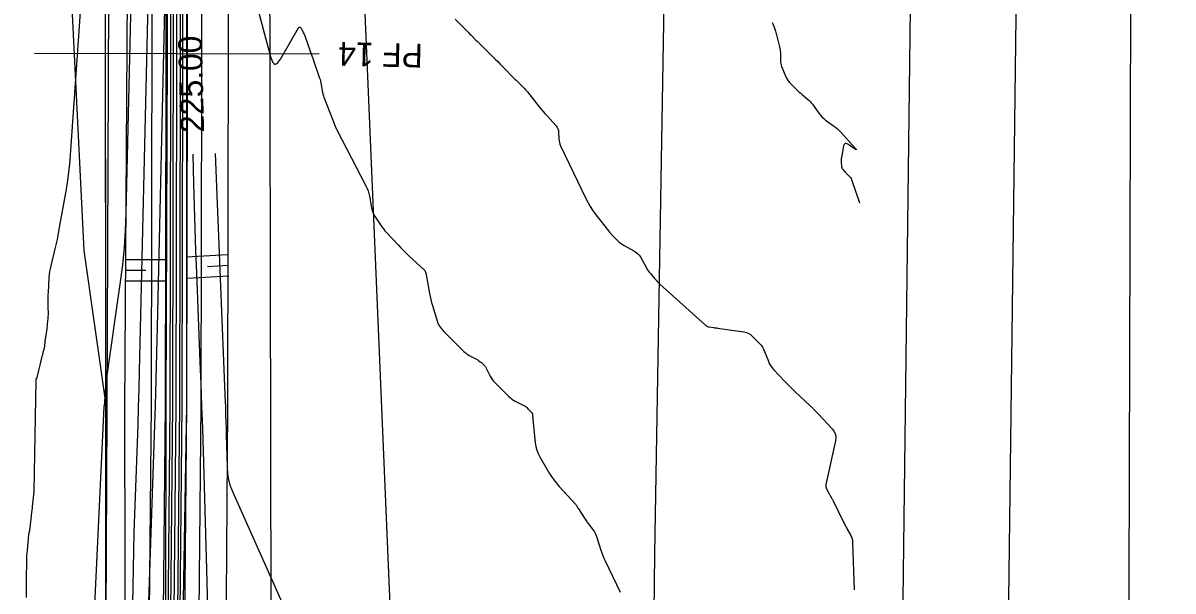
# Model space of a CAD drawing. Extents: x -534410 to -534262, y -1190162 to -1189584.
# Drawn here: x -534372.92 to -534324.46, y -1189828.34 to -1189804.39 of the extents above; entities that cross this region are included whole.
import ezdxf

# ---------------------------------------------------------------- set-up
doc = ezdxf.new("R2010")
doc.units = 0
for name, color, linetype in [('30', 7, 'Continuous'), ('31', 7, 'Continuous'), ('40', 7, 'Continuous'), ('_linie', 7, 'Continuous'), ('_N_osa', 7, 'Continuous'), ('_N_tenká', 7, 'Continuous'), ('_N_tenká_velmi', 7, 'Continuous'), ('_N_text', 7, 'Continuous'), ('_tenka', 7, 'Continuous'), ('_velmi_tenka', 7, 'Continuous'), ('Default', 7, 'Continuous'), ('Hranice parcel', 7, 'Continuous')]:
    doc.layers.add(name, color=color, linetype=linetype)

msp = doc.modelspace()

# ---------------------------------------------------------------- linework, layer by layer
at = {"layer": '30'}
for points in [[(-534370.569, -1189843.242), (-534369.518, -1189820.88), (-534369.518, -1189820.872), (-534369.517, -1189820.856), (-534369.517, -1189820.836), (-534369.516, -1189820.816), (-534369.516, -1189820.799), (-534369.515, -1189820.777), (-534369.515, -1189820.744), (-534369.514, -1189820.737), (-534369.51, -1189820.699), (-534369.509, -1189820.687), (-534369.509, -1189820.685), (-534369.507, -1189820.597), (-534369.506, -1189820.595), (-534369.501, -1189820.574), (-534369.5, -1189820.569), (-534369.499, -1189820.562), (-534369.498, -1189820.55), (-534369.497, -1189820.542), (-534369.497, -1189820.525), (-534369.496, -1189820.51), (-534369.495, -1189820.503), (-534369.49, -1189820.484), (-534369.488, -1189820.474), (-534369.482, -1189820.439), (-534369.481, -1189820.432), (-534369.48, -1189820.425), (-534369.479, -1189820.418), (-534369.479, -1189820.411), (-534369.457, -1189820.094), (-534369.447, -1189819.956), (-534369.431, -1189819.725), (-534369.427, -1189819.679), (-534369.423, -1189819.633), (-534369.418, -1189819.587), (-534369.412, -1189819.541), (-534368.811, -1189815.306), (-534368.719, -1189814.585), (-534368.649, -1189813.861), (-534368.6, -1189813.136), (-534368.572, -1189812.408), (-534367.974, -1189786.766)], [(-534367.679, -1189830.441), (-534367.447, -1189823.822), (-534367.391, -1189822.167), (-534367.34, -1189820.512), (-534367.294, -1189818.856), (-534367.253, -1189817.201), (-534366.829, -1189798.889), (-534366.819, -1189798.744), (-534366.799, -1189798.695), (-534366.77, -1189798.739), (-534366.73, -1189798.878), (-534366.506, -1189799.806), (-534366.479, -1189799.878), (-534366.444, -1189799.907), (-534366.402, -1189799.892), (-534366.351, -1189799.834), (-534366.134, -1189799.511), (-534366.086, -1189799.452), (-534366.051, -1189799.438), (-534366.029, -1189799.469), (-534366.02, -1189799.544), (-534365.914, -1189803.919)], [(-534363.773, -1189801.02), (-534362.475, -1189805.863), (-534362.398, -1189806.061), (-534362.304, -1189806.136), (-534362.194, -1189806.088), (-534362.068, -1189805.917), (-534361.308, -1189804.604), (-534361.285, -1189804.574), (-534361.262, -1189804.564), (-534361.239, -1189804.574), (-534361.216, -1189804.604), (-534361.126, -1189804.764), (-534361.104, -1189804.805), (-534361.084, -1189804.846), (-534361.066, -1189804.888), (-534361.049, -1189804.931), (-534360.731, -1189805.817), (-534360.725, -1189805.835), (-534360.714, -1189805.87), (-534360.708, -1189805.887), (-534360.427, -1189806.713), (-534360.405, -1189806.779), (-534360.387, -1189806.846), (-534360.372, -1189806.914), (-534360.359, -1189806.982), (-534360.315, -1189807.257), (-534360.302, -1189807.325), (-534360.286, -1189807.392), (-534360.266, -1189807.458), (-534360.242, -1189807.524), (-534359.746, -1189808.806), (-534359.745, -1189808.811), (-534359.742, -1189808.815), (-534359.74, -1189808.819), (-534359.737, -1189808.823), (-534359.725, -1189808.837), (-534359.723, -1189808.841), (-534359.72, -1189808.845), (-534359.718, -1189808.849), (-534359.716, -1189808.853), (-534359.707, -1189808.874), (-534359.703, -1189808.884), (-534359.698, -1189808.894), (-534358.473, -1189811.259), (-534358.423, -1189811.364), (-534358.382, -1189811.472), (-534358.349, -1189811.583), (-534358.324, -1189811.697), (-534358.236, -1189812.185), (-534358.213, -1189812.284), (-534358.18, -1189812.38), (-534358.138, -1189812.472), (-534358.085, -1189812.56), (-534357.857, -1189812.905), (-534357.798, -1189812.99), (-534357.736, -1189813.072), (-534357.671, -1189813.151), (-534357.602, -1189813.228), (-534357.102, -1189813.762), (-534356.994, -1189813.875), (-534356.885, -1189813.986), (-534356.773, -1189814.096), (-534356.66, -1189814.204), (-534356.01, -1189814.812), (-534355.994, -1189814.829), (-534355.981, -1189814.848), (-534355.971, -1189814.868), (-534355.964, -1189814.891), (-534355.939, -1189814.983), (-534355.934, -1189815.006), (-534355.928, -1189815.029), (-534355.923, -1189815.052), (-534355.919, -1189815.076), (-534355.789, -1189815.792), (-534355.764, -1189815.919), (-534355.736, -1189816.045), (-534355.704, -1189816.17), (-534355.669, -1189816.295), (-534355.486, -1189816.902), (-534355.435, -1189817.04), (-534355.369, -1189817.169), (-534355.287, -1189817.288), (-534355.19, -1189817.398), (-534354.347, -1189818.241), (-534354.295, -1189818.289), (-534354.24, -1189818.332), (-534354.182, -1189818.371), (-534354.121, -1189818.406), (-534353.782, -1189818.581), (-534353.763, -1189818.591), (-534353.744, -1189818.603), (-534353.727, -1189818.615), (-534353.71, -1189818.628), (-534353.643, -1189818.683), (-534353.626, -1189818.697), (-534353.609, -1189818.711), (-534353.593, -1189818.725), (-534353.576, -1189818.739), (-534353.49, -1189818.811), (-534353.472, -1189818.829), (-534353.455, -1189818.848), (-534353.44, -1189818.869), (-534353.428, -1189818.891), (-534353.232, -1189819.283), (-534353.192, -1189819.354), (-534353.148, -1189819.421), (-534353.098, -1189819.485), (-534353.043, -1189819.545), (-534352.443, -1189820.144), (-534352.384, -1189820.199), (-534352.32, -1189820.249), (-534352.253, -1189820.294), (-534352.182, -1189820.333), (-534351.789, -1189820.529), (-534351.767, -1189820.542), (-534351.746, -1189820.556), (-534351.726, -1189820.572), (-534351.708, -1189820.59), (-534351.637, -1189820.665), (-534351.619, -1189820.684), (-534351.601, -1189820.702), (-534351.582, -1189820.72), (-534351.564, -1189820.738), (-534351.488, -1189820.809), (-534351.472, -1189820.828), (-534351.459, -1189820.849), (-534351.451, -1189820.871), (-534351.448, -1189820.896), (-534351.438, -1189821.077), (-534351.436, -1189821.115), (-534351.433, -1189821.154), (-534351.429, -1189821.192), (-534351.426, -1189821.231), (-534351.336, -1189822.093), (-534351.312, -1189822.246), (-534351.272, -1189822.395), (-534351.217, -1189822.539), (-534351.145, -1189822.677), (-534350.745, -1189823.362), (-534350.652, -1189823.512), (-534350.551, -1189823.656), (-534350.442, -1189823.795), (-534350.326, -1189823.928), (-534349.634, -1189824.681), (-534349.621, -1189824.696), (-534349.61, -1189824.711), (-534349.599, -1189824.727), (-534349.59, -1189824.743), (-534349.553, -1189824.811), (-534349.543, -1189824.828), (-534349.534, -1189824.844), (-534349.524, -1189824.861), (-534349.513, -1189824.877), (-534349.232, -1189825.312), (-534349.192, -1189825.373), (-534349.15, -1189825.433), (-534349.108, -1189825.492), (-534349.064, -1189825.551), (-534348.886, -1189825.783), (-534348.845, -1189825.842), (-534348.808, -1189825.905), (-534348.778, -1189825.97), (-534348.753, -1189826.038), (-534348.571, -1189826.608), (-534348.532, -1189826.725), (-534348.488, -1189826.841), (-534348.44, -1189826.956), (-534348.389, -1189827.068), (-534347.756, -1189828.386)], [(-534341.357, -1189804.378), (-534341.328, -1189804.425), (-534341.303, -1189804.474), (-534341.283, -1189804.526), (-534341.21, -1189804.738), (-534341.193, -1189804.792), (-534341.177, -1189804.845), (-534341.162, -1189804.899), (-534341.149, -1189804.954), (-534341.034, -1189805.456), (-534341.021, -1189805.52), (-534341.012, -1189805.584), (-534341.006, -1189805.649), (-534341.005, -1189805.714), (-534341.005, -1189805.975), (-534341.001, -1189806.04), (-534340.992, -1189806.103), (-534340.976, -1189806.165), (-534340.953, -1189806.226), (-534340.756, -1189806.69), (-534340.72, -1189806.765), (-534340.677, -1189806.835), (-534340.627, -1189806.9), (-534340.57, -1189806.961), (-534340.318, -1189807.205), (-534340.263, -1189807.257), (-534340.207, -1189807.308), (-534340.15, -1189807.358), (-534340.092, -1189807.407), (-534339.86, -1189807.601), (-534339.803, -1189807.651), (-534339.75, -1189807.705), (-534339.701, -1189807.761), (-534339.655, -1189807.821), (-534339.384, -1189808.199), (-534339.321, -1189808.279), (-534339.252, -1189808.353), (-534339.177, -1189808.422), (-534339.097, -1189808.485), (-534338.764, -1189808.725), (-534338.682, -1189808.787), (-534338.604, -1189808.853), (-534338.53, -1189808.923), (-534338.46, -1189808.997), (-534337.857, -1189809.666), (-534337.816, -1189809.715), (-534337.807, -1189809.737), (-534337.83, -1189809.731), (-534337.885, -1189809.697), (-534338.168, -1189809.506), (-534338.231, -1189809.475), (-534338.281, -1189809.476), (-534338.318, -1189809.511), (-534338.34, -1189809.578), (-534338.43, -1189810.063), (-534338.437, -1189810.108), (-534338.441, -1189810.153), (-534338.442, -1189810.198), (-534338.44, -1189810.243), (-534338.425, -1189810.446), (-534338.419, -1189810.48), (-534338.409, -1189810.511), (-534338.394, -1189810.54), (-534338.374, -1189810.568), (-534338.278, -1189810.678), (-534338.257, -1189810.701), (-534338.236, -1189810.724), (-534338.214, -1189810.746), (-534338.191, -1189810.767), (-534338.061, -1189810.89), (-534338.056, -1189810.895), (-534338.051, -1189810.901), (-534338.042, -1189810.912), (-534338.039, -1189810.918), (-534338.036, -1189810.925), (-534338.021, -1189810.966), (-534338.014, -1189810.986), (-534337.672, -1189811.971)], [(-534365.768, -1189809.917), (-534365.737, -1189811.175), (-534365.712, -1189812.112), (-534365.684, -1189813.05), (-534365.652, -1189813.987), (-534365.616, -1189814.925), (-534365.465, -1189818.673), (-534365.429, -1189819.611), (-534365.395, -1189820.548), (-534365.365, -1189821.485), (-534365.337, -1189822.423), (-534365.18, -1189827.933), (-534365.145, -1189829.164)]]:
    msp.add_lwpolyline(points, dxfattribs=at)
at = {"layer": '31'}
for points in [[(-534368.595, -1189844.62), (-534368.288, -1189828.137), (-534368.272, -1189827.381), (-534368.254, -1189826.626), (-534368.232, -1189825.87), (-534368.207, -1189825.115), (-534368.101, -1189822.093), (-534368.075, -1189821.337), (-534368.052, -1189820.581), (-534368.031, -1189819.826), (-534368.012, -1189819.07), (-534367.528, -1189798.201), (-534367.485, -1189796.321), (-534367.441, -1189794.441), (-534367.397, -1189792.561), (-534367.353, -1189790.681), (-534367.147, -1189781.836), (-534367.116, -1189780.619), (-534367.081, -1189779.401), (-534367.07, -1189779.047)], [(-534372.78, -1189828.611), (-534372.773, -1189827.888), (-534372.772, -1189827.86), (-534372.771, -1189827.816), (-534372.771, -1189827.802), (-534372.764, -1189827.078), (-534372.761, -1189826.961), (-534372.756, -1189826.845), (-534372.749, -1189826.729), (-534372.739, -1189826.612), (-534372.676, -1189825.962), (-534372.674, -1189825.939), (-534372.67, -1189825.916), (-534372.666, -1189825.893), (-534372.662, -1189825.871), (-534372.642, -1189825.78), (-534372.638, -1189825.757), (-534372.634, -1189825.734), (-534372.63, -1189825.711), (-534372.627, -1189825.688), (-534372.547, -1189825.022), (-534372.537, -1189824.933), (-534372.527, -1189824.844), (-534372.517, -1189824.756), (-534372.508, -1189824.667), (-534372.455, -1189824.138), (-534372.454, -1189824.131), (-534372.451, -1189824.117), (-534372.45, -1189824.109), (-534372.373, -1189819.451), (-534372.372, -1189819.44), (-534372.37, -1189819.429), (-534372.367, -1189819.419), (-534372.362, -1189819.409), (-534372.341, -1189819.371), (-534372.336, -1189819.361), (-534372.332, -1189819.351), (-534372.329, -1189819.34), (-534372.326, -1189819.33), (-534372.098, -1189818.396), (-534372.091, -1189818.365), (-534372.083, -1189818.334), (-534372.075, -1189818.303), (-534372.067, -1189818.272), (-534372.034, -1189818.148), (-534372.026, -1189818.117), (-534372.02, -1189818.086), (-534372.014, -1189818.054), (-534372.01, -1189818.023), (-534371.989, -1189817.823), (-534371.984, -1189817.779), (-534371.979, -1189817.735), (-534371.973, -1189817.691), (-534371.966, -1189817.648), (-534371.912, -1189817.287), (-534371.905, -1189817.233), (-534371.898, -1189817.179), (-534371.891, -1189817.125), (-534371.886, -1189817.07), (-534371.864, -1189816.853), (-534371.86, -1189816.799), (-534371.857, -1189816.744), (-534371.855, -1189816.69), (-534371.855, -1189816.635), (-534371.857, -1189816.371), (-534371.857, -1189816.321), (-534371.858, -1189816.271), (-534371.858, -1189816.221), (-534371.859, -1189816.171), (-534371.861, -1189815.971), (-534371.861, -1189815.921), (-534371.861, -1189815.871), (-534371.859, -1189815.821), (-534371.856, -1189815.771), (-534371.815, -1189815.121), (-534371.805, -1189814.996), (-534371.789, -1189814.873), (-534371.767, -1189814.75), (-534371.74, -1189814.628), (-534371.551, -1189813.856), (-534371.511, -1189813.686), (-534371.474, -1189813.516), (-534371.44, -1189813.345), (-534371.408, -1189813.174), (-534371.096, -1189811.391), (-534371.039, -1189811.036), (-534370.99, -1189810.68), (-534370.952, -1189810.323), (-534370.922, -1189809.965), (-534369.649, -1189791.643)], [(-534354.713, -1189804.225), (-534354.19, -1189804.755), (-534354.145, -1189804.8), (-534354.101, -1189804.844), (-534354.056, -1189804.889), (-534354.011, -1189804.934), (-534353.833, -1189805.113), (-534353.788, -1189805.158), (-534353.743, -1189805.202), (-534353.698, -1189805.247), (-534353.653, -1189805.291), (-534353.124, -1189805.815), (-534353.021, -1189805.917), (-534352.918, -1189806.019), (-534352.816, -1189806.122), (-534352.713, -1189806.225), (-534352.19, -1189806.754), (-534352.146, -1189806.799), (-534352.101, -1189806.844), (-534352.056, -1189806.889), (-534352.012, -1189806.934), (-534351.833, -1189807.113), (-534351.789, -1189807.158), (-534351.746, -1189807.205), (-534351.704, -1189807.253), (-534351.664, -1189807.301), (-534351.166, -1189807.923), (-534351.089, -1189808.019), (-534351.011, -1189808.113), (-534350.931, -1189808.206), (-534350.85, -1189808.297), (-534350.457, -1189808.735), (-534350.413, -1189808.792), (-534350.381, -1189808.854), (-534350.361, -1189808.92), (-534350.352, -1189808.992), (-534350.338, -1189809.286), (-534350.331, -1189809.358), (-534350.317, -1189809.429), (-534350.296, -1189809.498), (-534350.268, -1189809.566), (-534349.192, -1189811.818), (-534349.111, -1189811.976), (-534349.022, -1189812.129), (-534348.925, -1189812.278), (-534348.82, -1189812.421), (-534348.256, -1189813.15), (-534348.209, -1189813.207), (-534348.161, -1189813.263), (-534348.111, -1189813.317), (-534348.06, -1189813.37), (-534347.849, -1189813.577), (-534347.794, -1189813.627), (-534347.737, -1189813.672), (-534347.677, -1189813.714), (-534347.614, -1189813.752), (-534347.182, -1189813.992), (-534347.094, -1189814.049), (-534347.016, -1189814.117), (-534346.948, -1189814.195), (-534346.891, -1189814.283), (-534346.651, -1189814.715), (-534346.614, -1189814.779), (-534346.573, -1189814.84), (-534346.529, -1189814.9), (-534346.483, -1189814.957), (-534346.291, -1189815.183), (-534346.242, -1189815.239), (-534346.191, -1189815.293), (-534346.139, -1189815.345), (-534346.085, -1189815.396), (-534344.156, -1189817.133), (-534344.122, -1189817.16), (-534344.085, -1189817.181), (-534344.046, -1189817.196), (-534344.004, -1189817.205), (-534343.83, -1189817.23), (-534343.787, -1189817.236), (-534343.743, -1189817.243), (-534343.7, -1189817.249), (-534343.656, -1189817.255), (-534342.55, -1189817.412), (-534342.449, -1189817.435), (-534342.356, -1189817.472), (-534342.27, -1189817.524), (-534342.191, -1189817.592), (-534341.893, -1189817.891), (-534341.822, -1189817.969), (-534341.762, -1189818.052), (-534341.71, -1189818.142), (-534341.668, -1189818.238), (-534341.513, -1189818.643), (-534341.471, -1189818.741), (-534341.419, -1189818.833), (-534341.359, -1189818.92), (-534341.289, -1189819.001), (-534340.821, -1189819.499), (-534340.718, -1189819.608), (-534340.613, -1189819.714), (-534340.506, -1189819.819), (-534340.398, -1189819.923), (-534339.763, -1189820.519), (-534339.625, -1189820.649), (-534339.605, -1189820.668), (-534339.586, -1189820.687), (-534339.567, -1189820.706), (-534339.548, -1189820.726), (-534339.399, -1189820.884), (-534338.821, -1189821.499), (-534338.736, -1189821.613), (-534338.684, -1189821.736), (-534338.665, -1189821.868), (-534338.681, -1189822.01), (-534339.088, -1189823.852), (-534339.094, -1189823.899), (-534339.092, -1189823.945), (-534339.081, -1189823.99), (-534339.062, -1189824.033), (-534338.946, -1189824.242), (-534338.932, -1189824.266), (-534338.919, -1189824.289), (-534338.905, -1189824.313), (-534338.891, -1189824.337), (-534338.836, -1189824.432), (-534338.823, -1189824.456), (-534338.81, -1189824.48), (-534338.797, -1189824.504), (-534338.785, -1189824.529), (-534338.329, -1189825.459), (-534338.295, -1189825.528), (-534338.26, -1189825.596), (-534338.225, -1189825.664), (-534338.189, -1189825.732), (-534338.043, -1189826.003), (-534338.01, -1189826.071), (-534337.987, -1189826.142), (-534337.971, -1189826.216), (-534337.965, -1189826.291), (-534337.898, -1189828.283)], [(-534364.821, -1189809.894), (-534364.399, -1189820.399), (-534364.395, -1189820.511), (-534364.391, -1189820.623), (-534364.387, -1189820.734), (-534364.384, -1189820.846), (-534364.371, -1189821.294), (-534364.368, -1189821.406), (-534364.365, -1189821.518), (-534364.362, -1189821.63), (-534364.359, -1189821.742), (-534364.324, -1189823.12), (-534364.305, -1189823.384), (-534364.26, -1189823.643), (-534364.189, -1189823.896), (-534364.093, -1189824.142), (-534361.369, -1189830.256)]]:
    msp.add_lwpolyline(points, dxfattribs=at)
at = {"layer": '_linie'}
for points in [[(-534366.12, -1189620.81), (-534364.52, -1189627.2), (-534365.69, -1189653.8), (-534366.76, -1189684.81), (-534368.14, -1189748.73), (-534368.38, -1189779.14), (-534368.65, -1189820.64), (-534368.59, -1189847.58), (-534367.2, -1189913.8)], [(-534363.12, -1189621.02), (-534362.79, -1189621.58), (-534361.82, -1189627.79), (-534363.46, -1189653.55), (-534365.47, -1189684.77), (-534366.65, -1189748.83), (-534366.75, -1189779.47), (-534366.9, -1189820.47), (-534366.95, -1189846.72), (-534366.338, -1189888.804), (-534363.85, -1189911.95), (-534357.07, -1189929.19), (-534352.334, -1189940.856)], [(-534359.03, -1189621.26), (-534359.41, -1189621.83), (-534360.84, -1189627.76), (-534362.92, -1189653.56), (-534364.64, -1189685), (-534365.94, -1189748.9), (-534366.02, -1189779.52), (-534366.03, -1189820.5), (-534366.48, -1189846.73), (-534365.511, -1189888.873), (-534362.72, -1189912.12), (-534356.62, -1189928.64), (-534351.589, -1189940.594)]]:
    msp.add_lwpolyline(points, dxfattribs=at)
at = {"layer": '_N_osa'}
msp.add_lwpolyline([(-534351.95, -1189940.722), (-534356.845, -1189928.915), (-534363.285, -1189912.035), (-534365.925, -1189888.838), (-534366.715, -1189846.725), (-534366.465, -1189820.485), (-534366.385, -1189779.495), (-534366.295, -1189748.865), (-534365.055, -1189684.885), (-534363.19, -1189653.555), (-534361.333, -1189627.822)], dxfattribs=at)
at = {"layer": '_N_tenká'}
for points in [[(-534352.92, -1189941.124), (-534357.821, -1189929.303), (-534364.313, -1189912.285), (-534366.973, -1189888.908), (-534367.765, -1189846.73), (-534367.515, -1189820.479), (-534367.435, -1189779.492), (-534367.345, -1189748.853), (-534366.104, -1189684.844), (-534364.238, -1189653.486), (-534362.424, -1189628.352), (-534361.782, -1189627.792)], [(-534352.089, -1189940.779), (-534356.984, -1189928.97), (-534363.432, -1189912.071), (-534366.074, -1189888.848), (-534366.865, -1189846.726), (-534366.615, -1189820.484), (-534366.535, -1189779.495), (-534366.445, -1189748.863), (-534365.205, -1189684.879), (-534363.34, -1189653.545), (-534361.483, -1189627.812)], [(-534351.812, -1189940.664), (-534356.706, -1189928.86), (-534363.138, -1189911.999), (-534365.775, -1189888.828), (-534366.565, -1189846.724), (-534366.315, -1189820.486), (-534366.235, -1189779.495), (-534366.145, -1189748.867), (-534364.905, -1189684.891), (-534363.04, -1189653.565), (-534361.184, -1189627.831)], [(-534350.98, -1189940.319), (-534355.869, -1189928.527), (-534362.257, -1189911.785), (-534364.876, -1189888.769), (-534365.665, -1189846.72), (-534365.415, -1189820.491), (-534365.335, -1189779.498), (-534365.245, -1189748.877), (-534364.006, -1189684.926), (-534362.142, -1189653.624), (-534360.329, -1189628.488), (-534360.884, -1189627.851)]]:
    msp.add_lwpolyline(points, dxfattribs=at)
at = {"layer": '_N_tenká_velmi'}
for points in [[(-534352.366, -1189940.894), (-534357.263, -1189929.081), (-534363.726, -1189912.142), (-534366.374, -1189888.868), (-534367.165, -1189846.727), (-534366.915, -1189820.482), (-534366.835, -1189779.494), (-534366.745, -1189748.86), (-534365.505, -1189684.867), (-534363.639, -1189653.525), (-534361.782, -1189627.792)], [(-534352.181, -1189940.817), (-534357.077, -1189929.007), (-534363.53, -1189912.095), (-534366.174, -1189888.855), (-534366.965, -1189846.726), (-534366.715, -1189820.484), (-534366.635, -1189779.494), (-534366.545, -1189748.862), (-534365.305, -1189684.875), (-534363.439, -1189653.539), (-534361.583, -1189627.805)], [(-534351.719, -1189940.626), (-534356.613, -1189928.823), (-534363.04, -1189911.975), (-534365.675, -1189888.822), (-534366.465, -1189846.724), (-534366.215, -1189820.486), (-534366.135, -1189779.496), (-534366.045, -1189748.868), (-534364.805, -1189684.895), (-534362.941, -1189653.571), (-534361.084, -1189627.838)], [(-534351.534, -1189940.549), (-534356.427, -1189928.749), (-534362.844, -1189911.928), (-534365.475, -1189888.808), (-534366.265, -1189846.723), (-534366.015, -1189820.488), (-534365.935, -1189779.496), (-534365.845, -1189748.87), (-534364.605, -1189684.903), (-534362.741, -1189653.585), (-534360.884, -1189627.851)]]:
    msp.add_lwpolyline(points, dxfattribs=at)
at = {"layer": '_N_text'}
msp.add_lwpolyline([(-534360.436, -1189805.703), (-534372.436, -1189805.676)], dxfattribs=at)
at = {"layer": '_tenka'}
for points in [[(-534349.13, -1189939.73), (-534354.63, -1189926.96), (-534362.03, -1189907.65), (-534364.521, -1189888.74), (-534364.47, -1189846.64), (-534364.29, -1189820.63), (-534364.22, -1189780.69), (-534363.18, -1189749.38), (-534362.5, -1189685.39), (-534360.27, -1189651.6), (-534357.03, -1189627.34), (-534354.77, -1189620.37)], [(-534366.12, -1189620.81), (-534364.52, -1189627.2), (-534365.69, -1189653.8), (-534366.76, -1189684.81), (-534368.14, -1189748.73), (-534368.38, -1189779.14), (-534368.65, -1189820.64), (-534368.59, -1189847.58), (-534367.2, -1189913.8)], [(-534366.12, -1189620.81), (-534364.52, -1189627.2), (-534365.69, -1189653.8), (-534366.76, -1189684.81), (-534368.14, -1189748.73), (-534368.38, -1189779.14), (-534368.65, -1189820.64), (-534368.59, -1189847.58), (-534367.2, -1189913.8)], [(-534363.12, -1189621.02), (-534362.79, -1189621.58), (-534361.82, -1189627.79), (-534363.46, -1189653.55), (-534365.47, -1189684.77), (-534366.65, -1189748.83), (-534366.75, -1189779.47), (-534366.9, -1189820.47), (-534366.95, -1189846.72), (-534366.338, -1189888.804), (-534363.85, -1189911.95), (-534357.07, -1189929.19), (-534352.334, -1189940.856)], [(-534363.12, -1189621.02), (-534362.79, -1189621.58), (-534361.82, -1189627.79), (-534363.46, -1189653.55), (-534365.47, -1189684.77), (-534366.65, -1189748.83), (-534366.75, -1189779.47), (-534366.9, -1189820.47), (-534366.95, -1189846.72), (-534366.338, -1189888.804), (-534363.85, -1189911.95), (-534357.07, -1189929.19), (-534352.334, -1189940.856)], [(-534359.03, -1189621.26), (-534359.41, -1189621.83), (-534360.84, -1189627.76), (-534362.92, -1189653.56), (-534364.64, -1189685), (-534365.94, -1189748.9), (-534366.02, -1189779.52), (-534366.03, -1189820.5), (-534366.48, -1189846.73), (-534365.511, -1189888.873), (-534362.72, -1189912.12), (-534356.62, -1189928.64), (-534351.589, -1189940.594)], [(-534359.03, -1189621.26), (-534359.41, -1189621.83), (-534360.84, -1189627.76), (-534362.92, -1189653.56), (-534364.64, -1189685), (-534365.94, -1189748.9), (-534366.02, -1189779.52), (-534366.03, -1189820.5), (-534366.48, -1189846.73), (-534365.511, -1189888.873), (-534362.72, -1189912.12), (-534356.62, -1189928.64), (-534351.589, -1189940.594)], [(-534368.65, -1189626.81), (-534368.65, -1189626.81), (-534367.31, -1189654.04), (-534367.67, -1189685.23), (-534369.56, -1189748.93), (-534369.48, -1189778.6), (-534369.45, -1189820.62), (-534369.45, -1189847.87), (-534371.206, -1189896.071), (-534372.39, -1189914.47)]]:
    msp.add_lwpolyline(points, dxfattribs=at)
at = {"layer": '_velmi_tenka'}
for p, q in [((-534368.612, -1189814.367), (-534366.879, -1189814.367)), ((-534364.304, -1189814.167), (-534366.053, -1189814.264)), ((-534368.612, -1189814.817), (-534367.746, -1189814.817)), ((-534364.279, -1189814.616), (-534365.154, -1189814.665)), ((-534368.612, -1189815.267), (-534366.879, -1189815.267)), ((-534364.255, -1189815.066), (-534366.004, -1189815.163))]:
    msp.add_line(p, q, dxfattribs=at)
at = {"layer": 'Default'}
for p, q in [((-534369.48, -1189778.6), (-534369.45, -1189820.62)), ((-534369.45, -1189820.62), (-534369.45, -1189847.87))]:
    msp.add_line(p, q, dxfattribs=at)
msp.add_lwpolyline([(-534349.13, -1189939.73), (-534354.63, -1189926.96), (-534362.03, -1189907.65), (-534364.521, -1189888.74), (-534364.47, -1189846.64), (-534364.29, -1189820.63), (-534364.22, -1189780.69), (-534363.18, -1189749.38), (-534362.5, -1189685.39), (-534360.27, -1189651.6), (-534357.03, -1189627.34), (-534354.77, -1189620.37)], dxfattribs=at)
at = {"layer": 'Hranice parcel'}
for p, q in [((-534369.38, -1189820.8), (-534369.14, -1189764.19)), ((-534369.75, -1189908.47), (-534369.38, -1189820.8))]:
    msp.add_line(p, q, dxfattribs=at)
for points in [[(-534347.07, -1189935.15), (-534347.12, -1189900.1), (-534346.3, -1189826.77), (-534344.77, -1189736.43), (-534342.85, -1189658.07), (-534338.334, -1189584.47)], [(-534338.84, -1189942.48), (-534336.49, -1189881.83), (-534334.78, -1189743.85), (-534331.691, -1189634.648)], [(-534334.89, -1189942.46), (-534332.03, -1189880.06), (-534330.32, -1189744.92), (-534328.5, -1189646.74), (-534327.899, -1189634.546)], [(-534330.63, -1189942.43), (-534326.4, -1189862.47), (-534326.07, -1189744.82), (-534325.13, -1189646.79), (-534324.459, -1189634.648)], [(-534359.48, -1189697.97), (-534362.6, -1189764.35), (-534362.34, -1189901.56)], [(-534359.48, -1189697.97), (-534360.42, -1189747.8), (-534359.17, -1189788.69), (-534356.86, -1189843.2), (-534358.53, -1189915.98)], [(-534369.38, -1189820.8), (-534370.35, -1189813.98), (-534372.65, -1189767.31), (-534373.49, -1189759.21)]]:
    msp.add_lwpolyline(points, dxfattribs=at)

# ---------------------------------------------------------------- texts
at = {"layer": '40'}
msp.add_text('225.00', height=1, rotation=91.3946, dxfattribs=at).set_placement((-534365.29, -1189809.007))
at = {"layer": '_N_text'}
msp.add_text('PF 14', height=1, rotation=178.6938, dxfattribs=at).set_placement((-534356.063, -1189805.275))

doc.saveas('drawing.dxf')
